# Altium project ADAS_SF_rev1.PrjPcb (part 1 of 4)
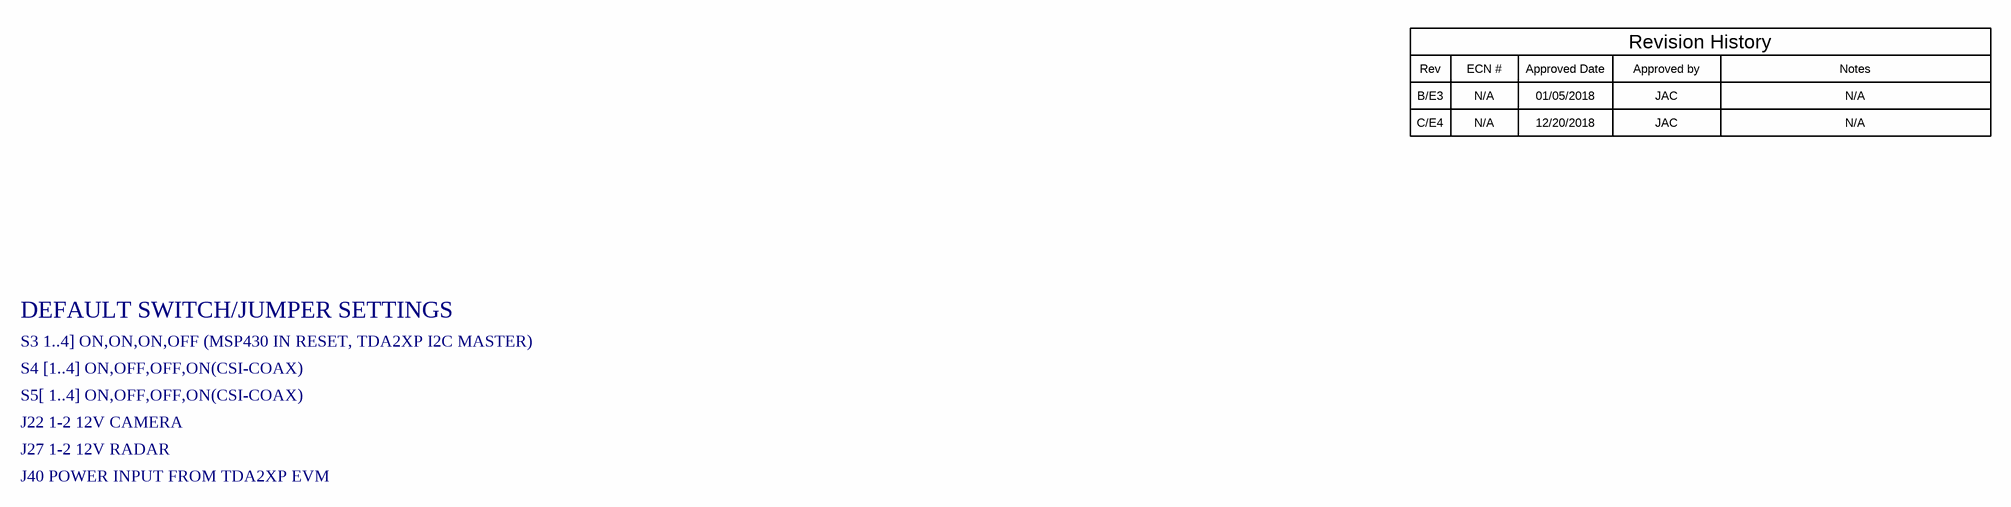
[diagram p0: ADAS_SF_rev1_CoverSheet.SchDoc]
CopyrightYear: 2018; PCB_Layout: Spectrum Digital; PCB_Rev: C; PRJ_Customer: Public Release; PRJ_Engineer: Spectrum Digital; PRJ_Number: 518520C; PRJ_Title: ADAS Sensor Fusion Board; SCH_Rev: E4; TechSupport: http://www.ti.com/support; TID: N/A
15 sheets, 822 parts. Net scope: global (net labels, ports and power ports of the same name join across sheets).
Board file: PCB1_test.PcbDoc
Sheets:
  ADAS_SF_rev1_CoverSheet.SchDoc
  ADAS_SF_Power_Battery_Input.SchDoc
  ADAS_SF_Power_Buck_5V.SchDoc
  ADAS_SF_Power_Boost_12V.SchDoc
  ADAS_SF_Power_Buck_3V3_1V8_1V1.SchDoc
  ADAS_SF_Data_MSP430.SchDoc
  ADAS_SF_Data_Deserializer_Camera.SchDoc
  ADAS_SF_Data_Deserializer_Radar.SchDoc
  ADAS_SF_Data_Radar_Mux.SchDoc
  ADAS_SF_Data_Connection_Radar_01.SchDoc
  ADAS_SF_Data_Connection_Radar_02.SchDoc
  ADAS_SF_Data_Connection_Cam_01.SchDoc
  ADAS_SF_Data_Connection_Cam_02.SchDoc
  ADAS_SF_Data_CSI2_Connector.SchDoc
  ADAS_SF_rev1_Hardware.SchDoc

## Sheet ADAS_SF_rev1_CoverSheet.SchDoc
size 431 x 279 mm; Date: Not shown in title block; ApprovedBy: Not shown in title block; CheckedBy: Not shown in title block; Author: Not shown in title block; CompanyName: Not shown in title block; Engineer: Not shown in title block; Organization: Not shown in title block; Address1: Not shown in title block; Address2: Not shown in title block; Address3: Not shown in title block; Address4: Not shown in title block; DocumentNumber: 1; Revision: Use project parameter SCH_Rev; SheetNumber: 1; SheetTotal: 15; PageSetup: Record=PageOptions¦CenterHorizontal=True¦CenterVertical=True¦PrintScale=1.00¦XCorrection=1.00¦YCorrection=1.00¦PrintKind=0¦BorderSize=5000000¦LeftOffset=0¦BottomOffset=0¦Orientation=2¦PaperLength=1000¦PaperWidth=1000¦Scale=100¦PaperSource=15¦PrintQuality=600¦MediaType=1¦DitherType=10¦PaperKind=Letter¦PrintScaleMode=1

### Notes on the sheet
- Rev
- B/E3
- ECN #
- N/A
- Approved Date
- 01/05/2018
- Approved by
- JAC
- Revision History
- Notes
- C/E4
- 12/20/2018
- S3 1..4] ON,ON,ON,OFF (MSP430 IN RESET, TDA2XP I2C MASTER)
- DEFAULT SWITCH/JUMPER SETTINGS
- S4 [1..4] ON,OFF,OFF,ON(CSI-COAX)
- S5[ 1..4] ON,OFF,OFF,ON(CSI-COAX)
- J22 1-2 12V CAMERA
- J27 1-2 12V RADAR
- J40 POWER INPUT FROM TDA2XP EVM

## Sheet ADAS_SF_Power_Battery_Input.SchDoc
size 431 x 279 mm; Date: Not shown in title block; ApprovedBy: Not shown in title block; CheckedBy: Not shown in title block; Author: Not shown in title block; CompanyName: Not shown in title block; Engineer: Not shown in title block; Organization: Not shown in title block; Address1: Not shown in title block; Address2: Not shown in title block; Address3: Not shown in title block; Address4: Not shown in title block; DocumentNumber: 1; Revision: Use project parameter SCH_Rev; SheetNumber: 2; SheetTotal: 15; PageSetup: Record=PageOptions¦CenterHorizontal=True¦CenterVertical=True¦PrintScale=1.00¦XCorrection=1.00¦YCorrection=1.00¦PrintKind=0¦BorderSize=5000000¦LeftOffset=0¦BottomOffset=0¦Orientation=2¦PaperLength=1000¦PaperWidth=1000¦Scale=100¦PaperSource=15¦PrintQuality=600¦MediaType=1¦DitherType=10¦PaperKind=Letter¦PrintScaleMode=1
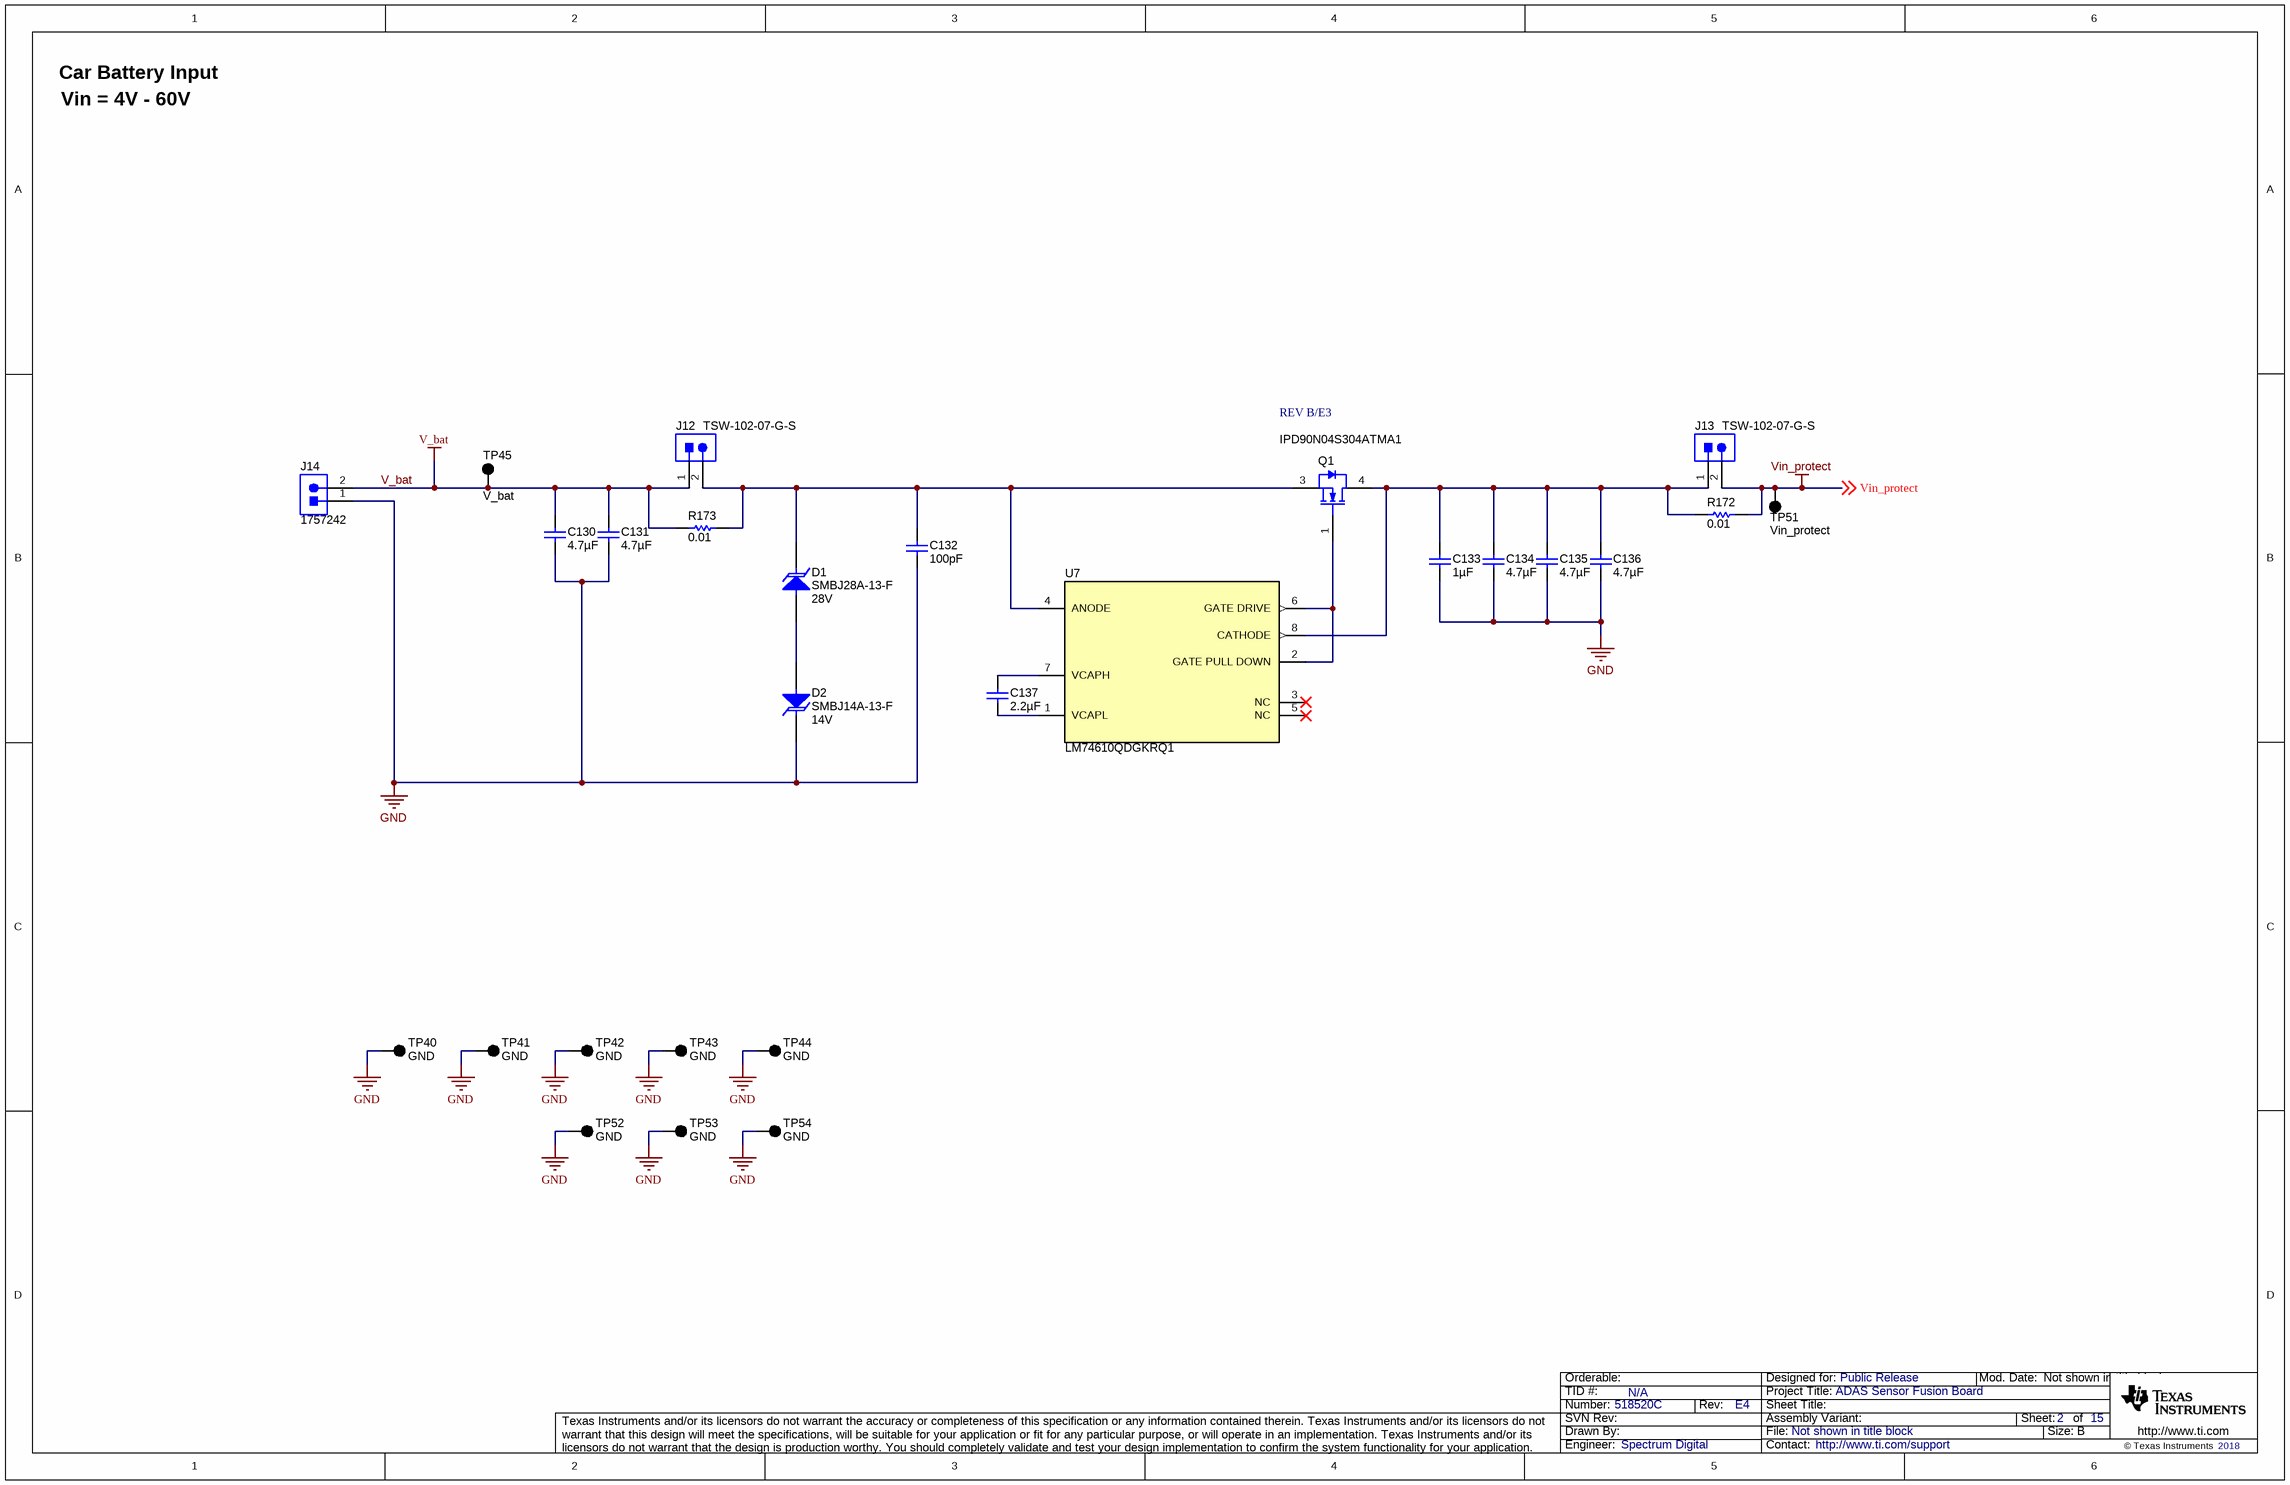
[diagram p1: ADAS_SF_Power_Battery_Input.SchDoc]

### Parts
C130  ValueDisplayed: 4.7µF  [1210_220]  (hidden comment: C3225X7S2A475K200AB)
C131  ValueDisplayed: 4.7µF  [1210_220]  (hidden comment: C3225X7S2A475K200AB)
C132  ValueDisplayed: 100pF  [0805_HV]  (hidden comment: 08055A101JAT2A)
C133  ValueDisplayed: 1µF  [0805_HV]  (hidden comment: GRM21BR71H105KA12L)
C134  ValueDisplayed: 4.7µF  [0805_HV]  (hidden comment: GRM21BC71H475KE11K)
C135  ValueDisplayed: 4.7µF  [0805_HV]  (hidden comment: GRM21BC71H475KE11K)
C136  ValueDisplayed: 4.7µF  [0805_HV]  (hidden comment: GRM21BC71H475KE11K)
C137  ValueDisplayed: 2.2µF  [0805_HV]  (hidden comment: C2012X5R1H225K125AB)
D1  SMBJ28A-13-F  value 28V  [SMB]
D2  SMBJ14A-13-F  value 14V  [SMB]
J12  TSW-102-07-G-S  [TSW-102-07-G-S]
J13  TSW-102-07-G-S  [TSW-102-07-G-S]
J14  1757242  [PHOENIX_1757242]
Q1  IPD90N04S304ATMA1  [DPAK]
R172  ValueDisplayed: 0.01  [KRL2012]  (hidden comment: KRL2012E-M-R010-F-T5)
R173  ValueDisplayed: 0.01  [KRL2012]  (hidden comment: KRL2012E-M-R010-F-T5)
TP40  GND  [Keystone5011]
TP41  GND  [Keystone5011]
TP42  GND  [Keystone5011]
TP43  GND  [Keystone5011]
TP44  GND  [Keystone5011]
TP45  V_bat  [Keystone5011]
TP51  Vin_protect  [Keystone5011]
TP52  GND  [Keystone5011]
TP53  GND  [Keystone5011]
TP54  GND  [Keystone5011]
U7  LM74610QDGKRQ1  [DGK0008A_N]

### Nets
GND: C130.2 C131.2 C132.2 C133.2 C134.2 C135.2 C136.2 D2.1(K) J14.1 TP40.1 TP41.1 TP42.1 TP43.1 TP44.1 TP52.1 TP53.1 TP54.1
V_bat: C130.1 C131.1 J12.1 J14.2 R173.1 TP45.1
Vin_protect: J13.2 R172.2 TP51.1 ; off-sheet Vin_protect
NetC132_1: C132.1 D1.1(K) J12.2 Q1.3(S) R173.2 U7.4(ANODE)
NetC133_1: C133.1 C134.1 C135.1 C136.1 J13.1 Q1.4(D) R172.1 U7.8(CATHODE)
NetC137_1: C137.1 U7.7(VCAPH)
NetC137_2: C137.2 U7.1(VCAPL)
NetD1_2: D1.2(A) D2.2(A)
NetQ1_1: Q1.1(G) U7.2(GATE_PULL_DOWN) U7.6(GATE_DRIVE)

Not connected (* = marked no-connect by the designer): U7 3(NC)* 5(NC)*

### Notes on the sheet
- Vin = 4V - 60V
- Car Battery Input
- REV B/E3

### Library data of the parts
C130 C131 = C3225X7S2A475K200AB: CAP, CERM, 4.7 µF, 100 V, +/- 10%, X7S, 1210; Manufacturer: TDK; Polarized: N; CompType: Capacitor; Value: 4.7uF; U/M: EA; Cap_F: 0.0000047; Tolerance_%: 10; ESR_ohm: 0.004236; Value1: 0.004236 ohm; VDC_V: 100; Value2: 100V; IRMS_A: 3.57337; TaMin_C: -55; TaMax_C: 125; SizeArea_mm2: 8; SizeAreaWB_mm2: 14.7; SizeX_mm: 3.2; SizeY_mm: 2.5; SizeZ_mm: 2.2; AEC Category: Q200
C132 = 08055A101JAT2A: CAP, CERM, 100 pF, 50 V, +/- 5%, C0G/NP0, 0805; Manufacturer: AVX; Polarized: N; CompType: Capacitor; Value: 100pF; U/M: EA; Cap_F: 0.0000000001; Tolerance_%: 5; ESR_ohm: 0.356; Value1: 0.356 ohm; VDC_V: 50; Value2: 50V; TaMin_C: -55; TaMax_C: 125; Cap_Case: 0805; AEC Category: Q200
C133 = GRM21BR71H105KA12L: CAP, CERM, 1 µF, 50 V, +/- 10%, X7R, 0805; Manufacturer: MuRata; Polarized: N; CompType: Capacitor; Value: 1uF; U/M: EA; Cap_F: 0.000001; Tolerance_%: 10; Value1: Unknown; VDC_V: 50; Value2: 50V; TaMin_C: -55; TaMax_C: 125; Cap_Case: 0805; SizeArea_mm2: 2.5; SizeAreaWB_mm2: 6.75; SizeX_mm: 2; SizeY_mm: 1.25; SizeZ_mm: 1.45; AEC Category: Q200
C134-C136 = GRM21BC71H475KE11K: CAP, CERM, 4.7 µF, 50 V, +/- 10%, X7S, 0805; Manufacturer: MuRata; Polarized: N; CompType: Capacitor; Value: 4.7uF; U/M: EA; Cap_F: 0.0000047; Tolerance_%: 10; Value1: Unknown; VDC_V: 50; Value2: 50V; TaMin_C: -55; TaMax_C: 125; Cap_Case: 0805; SizeArea_mm2: 2.5; SizeAreaWB_mm2: 6.75; SizeX_mm: 2; SizeY_mm: 1.25; SizeZ_mm: 1.45; AEC Category: Q200
C137 = C2012X5R1H225K125AB: CAP, CERM, 2.2 µF, 50 V, +/- 10%, X5R, 0805; Manufacturer: TDK; Polarized: N; CompType: Capacitor; Value: 2.2uF; U/M: EA; Cap_F: 0.0000022; Tolerance_%: 10; Value1: Unknown; VDC_V: 50; Value2: 50V; TaMin_C: -55; TaMax_C: 85; Cap_Case: 0805; AEC Category: Q200
D1 = SMBJ28A-13-F: Diode, TVS, Uni, 28 V, 600 W, SMB; Manufacturer: Diodes Inc.; U/M: EA; Power_W: 5; Vr_V: 28; Value1: 5W; AEC Category: Q101
D2 = SMBJ14A-13-F: Diode, TVS, Uni, 14 V, 600 W, SMB; Manufacturer: Diodes Inc.; U/M: EA; Power_W: 5; Vr_V: 14; Value1: 5W; AEC Category: Q101
J12 J13 = TSW-102-07-G-S: Header, 100mil, 2x1, Gold, TH; Manufacturer: Samtec; SymbolCreator: a0412235; Pitch_mm: 2.54; Gender: Male; Shrouded: N; Row_Count: 1; Current_A: 6.3; Voltage_V: 550; Cert_CSA: Y
J14 = 1757242: Header (Shrouded), 5.08 mm, 2x1, Tin, R/A, TH; Manufacturer: Phoenix Contact; SymbolCreator: a0412235
Q1 = IPD90N04S304ATMA1: MOSFET, N-CH, 40 V, 90 A, AEC-Q101, DPAK; Manufacturer: Infineon Technologies; Alternate Manufacturer: None; U/M: EA; ChType: N; Value: 40V; VdsMax_V: 40; Value1: ? ohm; Value2: 60 nC; QgTyp_nC: 60; Vgs_V: 20; IdsMax_A: 90; AEC Category: Q101; AEC Qualified: Y
R172 R173 = KRL2012E-M-R010-F-T5: RES, 0.01, 1%, 1 W, AEC-Q200 Grade 0, 0508; Manufacturer: Susumu Co Ltd; CompType: Resistor; Value: 0.01; Value_Code: R010; Tolerance_%: 1; Value2: 1W; TempCo: 25 ppm/C; EIA_Code: E96; U/M: EA; AEC Category: Q200; AEC Qualified: Y; AEC Grade: 0
TP40-TP45 TP51-TP54 = 5011: Test Point, Multipurpose, Black, TH; Manufacturer: Keystone; CompType: Test Point Loop; U/M: EA
U7 = LM74610QDGKRQ1: Smart Diode Controller, DGK0008A; Manufacturer: Texas Instruments; SymbolCreator: Altium; CompType: IC; U/M: EA

## Sheet ADAS_SF_Power_Buck_5V.SchDoc
size 431 x 279 mm; Date: Not shown in title block; ApprovedBy: Not shown in title block; CheckedBy: Not shown in title block; Author: Not shown in title block; CompanyName: Not shown in title block; Engineer: Not shown in title block; Organization: Not shown in title block; Address1: Not shown in title block; Address2: Not shown in title block; Address3: Not shown in title block; Address4: Not shown in title block; DocumentNumber: 1; Revision: Use project parameter SCH_Rev; SheetNumber: 3; SheetTotal: 15; PageSetup: Record=PageOptions¦CenterHorizontal=True¦CenterVertical=True¦PrintScale=0.66¦XCorrection=1.00¦YCorrection=1.00¦PrintKind=0¦BorderSize=5000000¦LeftOffset=0¦BottomOffset=0¦Orientation=2¦PaperLength=1000¦PaperWidth=1000¦Scale=100¦PaperSource=15¦PrintQuality=600¦MediaType=1¦DitherType=10¦PrintScaleMode=1¦PaperKind=Letter
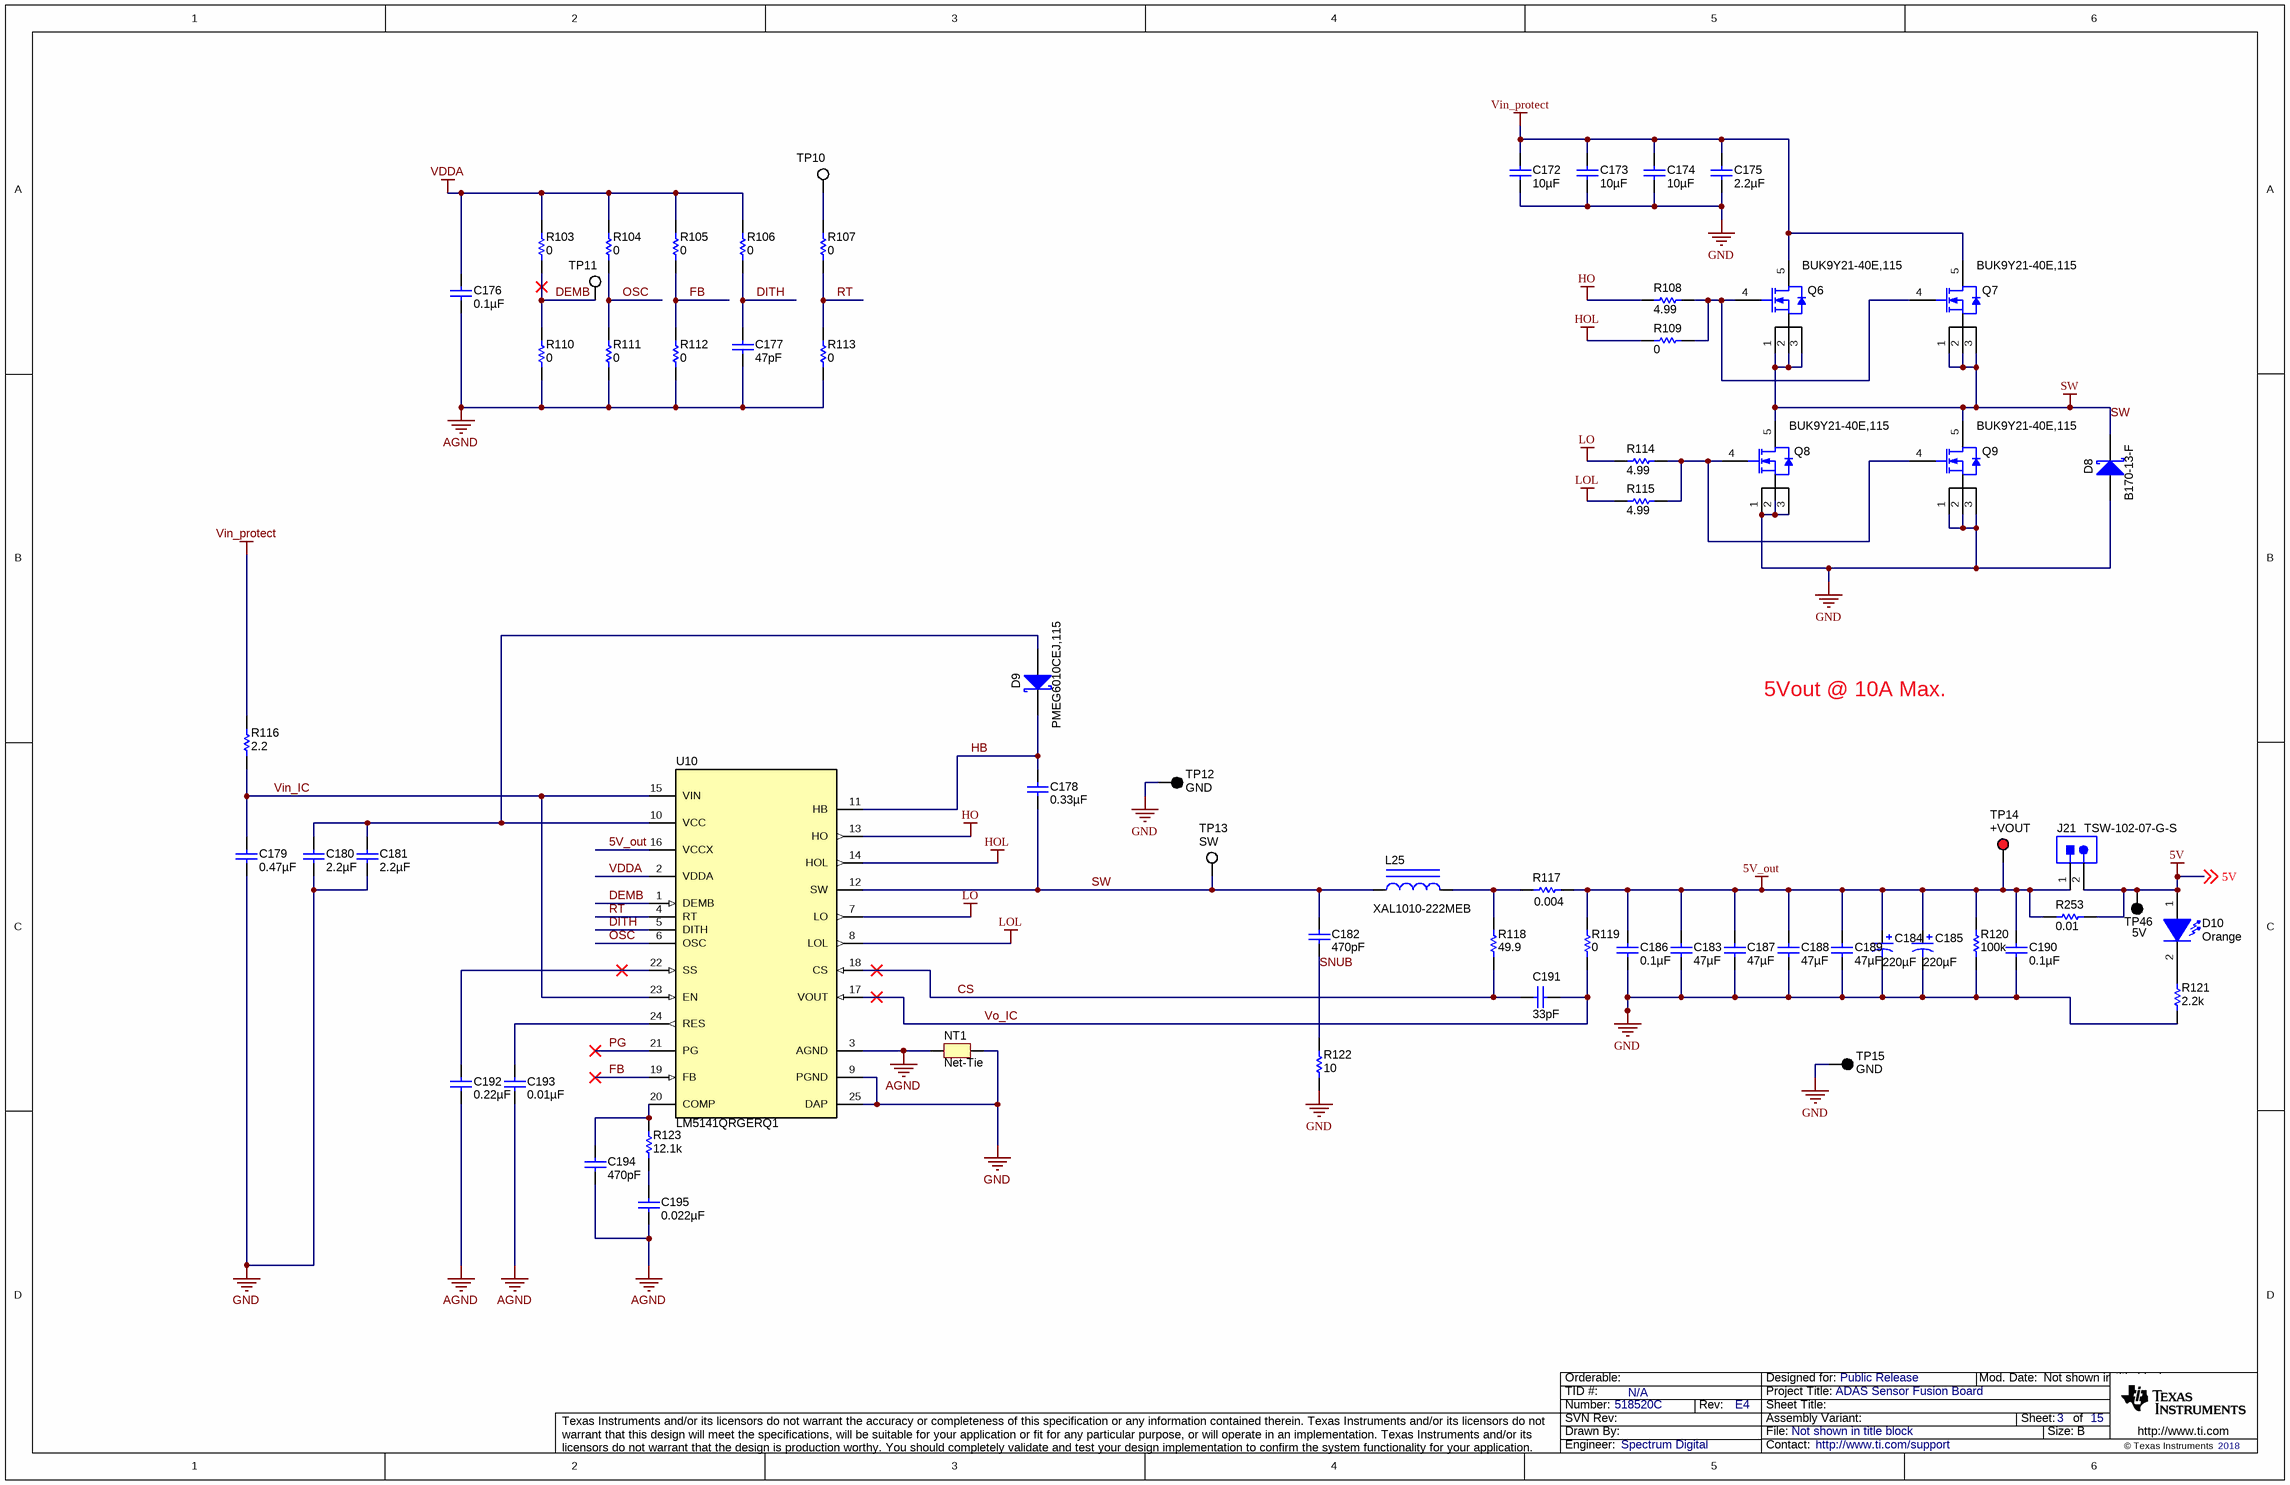
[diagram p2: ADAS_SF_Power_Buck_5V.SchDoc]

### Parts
C172  ValueDisplayed: 10µF  [1206_190]  (hidden comment: CGA5L3X5R1H106K160AB)
C173  ValueDisplayed: 10µF  [1206_190]  (hidden comment: CGA5L3X5R1H106K160AB)
C174  ValueDisplayed: 10µF  [1206_190]  (hidden comment: CGA5L3X5R1H106K160AB)
C175  2.2µF  [1206]
C176  ValueDisplayed: 0.1µF  [0402]  (hidden comment: GCM155R71H104KE02D)
C177  ValueDisplayed: 47pF  [0402]  (hidden comment: GRM1555C1E470JA01D)
C178  ValueDisplayed: 0.33µF  [0805_HV]  (hidden comment: GRM21AR72A334KAC5L)
C179  ValueDisplayed: 0.47µF  [0805_HV]  (hidden comment: GRM21BR72A474KA73L)
C180  ValueDisplayed: 2.2µF  [0603_HV]  (hidden comment: C0603C225M8PACTU)
C181  ValueDisplayed: 2.2µF  [0603_HV]  (hidden comment: C0603C225M8PACTU)
C182  ValueDisplayed: 470pF  [0805_HV]  (hidden comment: 08051A471JAT2A)
C183  ValueDisplayed: 47µF  [1206_180]  (hidden comment: GRM31CR61A476KE15L)
C184  ValueDisplayed: 220µF  [CAPSMT_62_H70]  (hidden comment: APXA6R3ARA221MH70G)
C185  ValueDisplayed: 220µF  [CAPSMT_62_H70]  (hidden comment: APXA6R3ARA221MH70G)
C186  ValueDisplayed: 0.1µF  [0603L]  (hidden comment: GRM188R72A104KA35D)
C187  ValueDisplayed: 47µF  [1206_180]  (hidden comment: GRM31CR61A476KE15L)
C188  ValueDisplayed: 47µF  [1206_180]  (hidden comment: GRM31CR61A476KE15L)
C189  ValueDisplayed: 47µF  [1206_180]  (hidden comment: GRM31CR61A476KE15L)
C190  ValueDisplayed: 0.1µF  [0603L]  (hidden comment: GRM188R72A104KA35D)
C191  ValueDisplayed: 33pF  [0603L]  (hidden comment: 06031A330JAT2A)
C192  ValueDisplayed: 0.22µF  [0402]  (hidden comment: GRM155R61A224KE19D)
C193  ValueDisplayed: 0.01µF  [0402]  (hidden comment: GCM155R71H103KA55D)
C194  ValueDisplayed: 470pF  [0402]  (hidden comment: GRM1555C1E471JA01D)
C195  ValueDisplayed: 0.022µF  [0402]  (hidden comment: GRM155R71C223KA01D)
D8  B170-13-F  [SMA]
D9  PMEG6010CEJ,115  [SOD-323F]
D10  value Orange  [LED_SMLP12_ORANGE]  (hidden comment: SML-P12DTT86)
J21  TSW-102-07-G-S  [TSW-102-07-G-S]
L25  XAL1010-222MEB  [XAL1010]
NT1  Net-Tie  [Net-Tie_10mil]  (net tie, no BOM)
Q6  BUK9Y21-40E,115  [LFPAK56]
Q7  BUK9Y21-40E,115  [LFPAK56]
Q8  BUK9Y21-40E,115  [LFPAK56]
Q9  BUK9Y21-40E,115  [LFPAK56]
R103  ValueDisplayed: 0  [0402]  (hidden comment: CRCW04020000Z0ED)
R104  ValueDisplayed: 0  [0402]  (hidden comment: CRCW04020000Z0ED)
R105  ValueDisplayed: 0  [0402]  (hidden comment: CRCW04020000Z0ED)
R106  ValueDisplayed: 0  [0402]  (hidden comment: CRCW04020000Z0ED)
R107  ValueDisplayed: 0  [0402]  (hidden comment: CRCW04020000Z0ED)
R108  ValueDisplayed: 4.99  [0603L]  (hidden comment: CRCW06034R99FKEA)
R109  ValueDisplayed: 0  [0603L]  (hidden comment: CRCW06030000Z0EA)
R110  ValueDisplayed: 0  [0402]  (hidden comment: CRCW04020000Z0ED)
R111  ValueDisplayed: 0  [0402]  (hidden comment: CRCW04020000Z0ED)
R112  ValueDisplayed: 0  [0402]  (hidden comment: CRCW04020000Z0ED)
R113  ValueDisplayed: 0  [0402]  (hidden comment: CRCW04020000Z0ED)
R114  ValueDisplayed: 4.99  [0603L]  (hidden comment: CRCW06034R99FKEA)
R115  ValueDisplayed: 4.99  [0603L]  (hidden comment: CRCW06034R99FKEA)
R116  ValueDisplayed: 2.2  [0603L]  (hidden comment: CRCW06032R20JNEA)
R117  value 0.004  [2010]  (hidden comment: PMR50HZPFV4L00)
R118  ValueDisplayed: 49.9  [0603L]  (hidden comment: CRCW060349R9FKEA)
R119  ValueDisplayed: 0  [0603L]  (hidden comment: CRCW06030000Z0EA)
R120  ValueDisplayed: 100k  [0805_HV]  (hidden comment: CRCW0805100KFKEA)
R121  ValueDisplayed: 2.2k  [0402]  (hidden comment: CRCW04022K20JNED)
R122  ValueDisplayed: 10  [2010]  (hidden comment: CRCW201010R0JNEF)
R123  ValueDisplayed: 12.1k  [0402]  (hidden comment: CRCW040212K1FKED)
R253  ValueDisplayed: 0.01  [KRL2012]  (hidden comment: KRL2012E-M-R010-F-T5)
TP10  5012  [Keystone5012]  (value not drawn)
TP11  5012  [Keystone5012]  (value not drawn)
TP12  GND  [Keystone5011]
TP13  SW  [Keystone5012]
TP14  +VOUT  [Keystone5010]
TP15  GND  [Keystone5011]
TP46  5V  [Keystone5011]
U10  LM5141QRGERQ1  [RGE0024H]

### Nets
5V: D10.1(A) J21.2 R253.2 TP46.1 ; off-sheet 5V
5V_out: C183.1 C184.1(+) C185.1(+) C186.2 C187.1 C188.1 C189.1 C190.2 J21.1 R117.2 R119.2 R120.2 R253.1 TP14.1 U10.16(VCCX)
AGND: C176.2 C177.1 C192.2 C193.2 C194.1 C195.2 NT1.2 R110.1 R111.1 R112.1 R113.1 U10.3(AGND)
GND: C172.2 C173.2 C174.2 C175.2 C179.1 C180.2 C181.1 C183.2 C184.2(-) C185.2(-) C186.1 C187.2 C188.2 C189.2 C190.1 D8.2(A) NT1.1 Q8.1(S) Q8.2(S) Q8.3(S) Q9.1(S) Q9.2(S) Q9.3(S) R120.1 R121.2 R122.1 TP12.1 TP15.1 U10.9(PGND) U10.25(DAP)
HO: R108.1 U10.13(HO)
HOL: R109.1 U10.14(HOL)
LO: R114.1 U10.7(LO)
LOL: R115.1 U10.8(LOL)
SW: C178.1 C182.2 D8.1(K) L25.1 Q6.1(S) Q6.2(S) Q6.3(S) Q7.1(S) Q7.2(S) Q7.3(S) Q8.5(D) Q9.5(D) TP13.1 U10.12(SW)
VDDA: C176.1 R103.2 R104.2 R105.2 R106.2 U10.2(VDDA)
Vin_protect: C172.1 C173.1 C174.1 C175.1 Q6.5(D) Q7.5(D) R116.2
CS: C191.2 R118.1 U10.18(CS)
DEMB: R103.1 R110.2 TP11.1 U10.1(DEMB)
DITH: C177.2 R106.1 U10.5(DITH)
FB: R105.1 R112.2 U10.19(FB)
HB: C178.2 D9.1(K) U10.11(HB)
OSC: R104.1 R111.2 U10.6(OSC)
PG: U10.21(PG)
RT: R107.1 R113.2 U10.4(RT)
SNUB: C182.1 R122.2
Vin_IC: C179.2 R116.1 U10.15(VIN) U10.23(EN)
Vo_IC: C191.1 R119.1 U10.17(VOUT)
NetC180_1: C180.1 C181.2 D9.2(A) U10.10(VCC)
NetC192_1: C192.1 U10.22(SS)
NetC193_1: C193.1 U10.24(RES)
NetC194_2: C194.2 R123.2 U10.20(COMP)
NetC195_1: C195.1 R123.1
NetD10_2: D10.2(K) R121.1
NetL25_2: L25.2 R117.1 R118.2
NetQ6_4: Q6.4(G) Q7.4(G) R108.2 R109.2
NetQ8_4: Q8.4(G) Q9.4(G) R114.2 R115.2
NetR107_2: R107.2 TP10.1

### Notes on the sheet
- 5Vout @ 10A Max.

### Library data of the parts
C172-C174 = CGA5L3X5R1H106K160AB: CAP, CERM, 10 µF, 50 V, +/- 10%, X5R, 1206_190; Manufacturer: TDK; Polarized: N; CompType: Capacitor; Value: 10uF; U/M: EA; Cap_F: 0.00001; Tolerance_%: 10; Value1: Unknown; VDC_V: 50; Value2: 50V; TaMin_C: -55; TaMax_C: 85; Cap_Case: 1206
C175 = CL31B225KCHSNNE: CAP CER 2.2UF 100V 10% X7R 1206; Manufacturer: Samsung Electro-Mechanics America, Inc; SymbolVersion: use current date i.e. 2008-05-20; SymbolCreator: Use a-id; CompType: Used in some BOM reports.  Useful for finding later.; U/M: EA, IN, or GM
C176 = GCM155R71H104KE02D: CAP, CERM, 0.1 µF, 50 V, +/- 10%, X7R, AEC-Q200 Grade 1, 0402; Manufacturer: MuRata; Polarized: N; CompType: Capacitor; Value: 0.1uF; U/M: EA; Cap_F: 0.0000001; Tolerance_%: 10; Value1: Unknown; VDC_V: 50; Value2: 50V; TaMin_C: -55; TaMax_C: 125; AEC Category: Q200; AEC Qualified: Y; AEC Grade: 1; SizeArea_mm2: 0.5; SizeAreaWB_mm2: 3; SizeZ_mm: 0.6
C177 = GRM1555C1E470JA01D: CAP, CERM, 47 pF, 25 V, +/- 5%, C0G/NP0, 0402; Manufacturer: MuRata; Polarized: N; CompType: Capacitor; Value: 47pF; U/M: EA; Cap_F: 0.000000000047; Tolerance_%: 5; Value1: Unknown; VDC_V: 25; Value2: 25V; TaMin_C: -55; TaMax_C: 125; AEC Category: Q200
C178 = GRM21AR72A334KAC5L: CAP, CERM, 0.33 µF, 100 V, +/- 10%, X7R, 0805; Manufacturer: MuRata; Polarized: N; CompType: Capacitor; Value: 0.33uF; U/M: EA; Cap_F: 0.00000033; Tolerance_%: 10; Value1: Unknown; VDC_V: 100; Value2: 100V; TaMin_C: -55; TaMax_C: 125; Cap_Case: 0805
C179 = GRM21BR72A474KA73L: CAP, CERM, 0.47uF, 100V, +/-10%, X7R, 0805; Manufacturer: MuRata; Polarized: N; CompType: Capacitor; U/M: EA; Cap_F: 0.00000047; Tolerance_%: 10; Value1: Unknown; VDC_V: 100; TaMin_C: -55; TaMax_C: 125; Cap_Case: 0805
C180 C181 = C0603C225M8PACTU: CAP, CERM, 2.2 µF, 10 V, +/- 20%, X5R, 0603; Manufacturer: Kemet; Polarized: N; CompType: Capacitor; Value: 2.2uF; U/M: EA; Cap_F: 0.0000022; Tolerance_%: 20; Value1: Unknown; VDC_V: 10; Value2: 10V; TaMin_C: -55; TaMax_C: 85; Cap_Case: 0603
C182 = 08051A471JAT2A: CAP, CERM, 470 pF, 100 V, +/- 5%, C0G/NP0, 0805; Manufacturer: AVX; Polarized: N; CompType: Capacitor; Value: 470pF; U/M: EA; Cap_F: 0.00000000047; Tolerance_%: 5; ESR_ohm: 0.159; Value1: 0.159 ohm; VDC_V: 100; Value2: 100V; TaMin_C: -55; TaMax_C: 125; Cap_Case: 0805; SizeArea_mm2: 2.5; SizeAreaWB_mm2: 6.75; SizeX_mm: 2; SizeY_mm: 1.25; SizeZ_mm: 1.45; AEC Category: Q200
C183 C187-C189 = GRM31CR61A476KE15L: CAP, CERM, 47 µF, 10 V, +/- 10%, X5R, 1206; Manufacturer: MuRata; Polarized: N; CompType: Capacitor; Value: 47uF; U/M: EA; Cap_F: 0.000047; Tolerance_%: 10; Value1: Unknown; Value2: 10V; TaMin_C: -55; TaMax_C: 85; Cap_Case: 1206; SizeArea_mm2: 5.12; SizeAreaWB_mm2: 10.92; SizeX_mm: 3.2; SizeY_mm: 1.6; SizeZ_mm: 1.8; AEC Category: Q200
C184 C185 = APXA6R3ARA221MH70G: CAP, AL, 220 µF, 6.3 V, +/- 20%, 0.025 ohm, SMD; Manufacturer: Chemi-Con; Polarized: Y; CompType: Capacitor; Value: 220uF; U/M: EA; Cap_F: 0.00022; Tolerance_%: 20; VDC_V: 6.3; Value2: 6.3V; ESR_ohm: 0.025; IRMS_A: 3.02; TaMin_C: -55; TaMax_C: 105; Cap_Case: H70
C186 C190 = GRM188R72A104KA35D: CAP, CERM, 0.1uF, 100V, +/-10%, X7R, 0603; Manufacturer: MuRata; Polarized: N; CompType: Capacitor; U/M: EA; Cap_F: 0.0000001; Tolerance_%: 10; Value1: Unknown; VDC_V: 100; TaMin_C: -55; TaMax_C: 125; Cap_Case: 0603
C191 = 06031A330JAT2A: CAP, CERM, 33 pF, 100 V, +/- 5%, C0G/NP0, 0603; Manufacturer: AVX; Polarized: N; CompType: Capacitor; Value: 33pF; U/M: EA; Cap_F: 0.000000000033; Tolerance_%: 5; ESR_ohm: 0.209; Value1: 0.209 ohm; VDC_V: 100; Value2: 100V; TaMin_C: -55; TaMax_C: 125; Cap_Case: 0603
C192 = GRM155R61A224KE19D: CAP, CERM, 0.22 µF, 10 V, +/- 10%, X5R, 0402; Manufacturer: MuRata; Polarized: N; CompType: Capacitor; Value: 0.22uF; U/M: EA; Cap_F: 0.00000022; Tolerance_%: 10; Value1: Unknown; Value2: 10V; TaMin_C: -55; TaMax_C: 85; SizeArea_mm2: 0.5; SizeAreaWB_mm2: 3; SizeX_mm: 1; SizeZ_mm: 0.6; AEC Category: Q200
C193 = GCM155R71H103KA55D: CAP, CERM, 0.01uF, 50V, +/-10%, C0G/NP0, 0402; Manufacturer: MuRata; Polarized: N; CompType: Capacitor; U/M: EA; Cap_F: 0.00000001; Tolerance_%: 10; Value1: Unknown; VDC_V: 50; TaMin_C: -55; TaMax_C: 125
C194 = GRM1555C1E471JA01D: CAP, CERM, 470 pF, 25 V, +/- 5%, C0G/NP0, 0402; Manufacturer: MuRata; Polarized: N; CompType: Capacitor; Value: 470pF; U/M: EA; Cap_F: 0.00000000047; Tolerance_%: 5; Value1: Unknown; VDC_V: 25; Value2: 25V; TaMin_C: -55; TaMax_C: 125; SizeArea_mm2: 0.5; SizeAreaWB_mm2: 3; SizeX_mm: 1; SizeZ_mm: 0.6; AEC Category: Q200
C195 = GRM155R71C223KA01D: CAP, CERM, 0.022 µF, 16 V, +/- 10%, X7R, 0402; Manufacturer: MuRata; Polarized: N; CompType: Capacitor; Value: 0.022uF; U/M: EA; Cap_F: 0.000000022; Tolerance_%: 10; Value1: Unknown; VDC_V: 16; Value2: 16V; TaMin_C: -55; TaMax_C: 125; SizeArea_mm2: 0.5; SizeAreaWB_mm2: 3; SizeX_mm: 1; SizeZ_mm: 0.6; AEC Category: Q200
D8 = B170-13-F: Diode, Schottky, 70V, 1A, SMA; Manufacturer: Diodes Inc.; U/M: EA; Vr_V: 70; Io_A: 1; Vf_V: 0.79; Value2: 0.79V; TJmax_C: 150; RJC_CperW: 25
D9 = PMEG6010CEJ,115: Diode, Schottky, 60 V, 1 A, SOD-323F; Manufacturer: NXP Semiconductor; U/M: EA; Vf_V: 0.66; Value: 60V; Value1: 1A; Value2: 0.66V; Io_A: 1; Vr_V: 60; TJmax_C: 150
D10 = SML-P12DTT86: LED, Orange, SMD; Manufacturer: Rohm; Type: InGaN; Vf_V: 2.1; Value2: 2.1V; Io_A: 0.02; Tjmax_C: 85; Value1: W; U/M: EA
J21 = TSW-102-07-G-S: as J12 on sheet ADAS_SF_Power_Battery_Input
L25 = XAL1010-222MEB: Inductor, Shielded, Composite, 2.2 µH, 32 A, 0.00255 ohm, SMD; Manufacturer: Coilcraft; Value: 2.2uH; Ind_H: 2.2E-6; ValueDisplayed: 2.2µH; Imax_A: 32; Irms: 32A @ 40C rise; Isat: 34A @ 30% inductance drop; Value2: 32A
NT1 = Net-Tie: Single point connection between nets.; SymbolCreator: codlsc
Q6-Q9 = BUK9Y21-40E,115: MOSFET, N-CH, 40 V, 33 A, AEC-Q101, SOT669; Manufacturer: NXP Semiconductor; Alternate Manufacturer: None; SymbolCreator: a0412235; U/M: EA; ChType: N; Value: 40V; VdsMax_V: 40; Value1: ? ohm; Value2: 7 nC; QgTyp_nC: 7; Vgs_V: 10; IdsMax_A: 33; AEC Category: Q101; AEC Qualified: Y
R103-R107 R110-R113 = CRCW04020000Z0ED: RES, 0, 5%, 0.063 W, 0402; Manufacturer: Vishay-Dale; CompType: Resistor; Value: 0; Value_Code: 0000; Tolerance_%: 5; Power_W: 0.063; Value2: 0.063W; VDC_V: 50; TempCo: 200 ppm/C; EIA_Code: E24; U/M: EA; AEC Category: Q200
R108 R114 R115 = CRCW06034R99FKEA: RES, 4.99, 1%, 0.1 W, 0603; Manufacturer: Vishay-Dale; CompType: Resistor; Value: 4.99; Value_Code: 4R99; Tolerance_%: 1; Power_W: 0.1; Value2: 0.1W; VDC_V: 75; TempCo: 100 ppm/C; EIA_Code: E96; U/M: EA
R109 R119 = CRCW06030000Z0EA: RES, 0, 5%, 0.1 W, 0603; Manufacturer: Vishay-Dale; CompType: Resistor; Value: 0; Value_Code: 0000; Tolerance_%: 5; Power_W: 0.1; Value2: 0.1W; VDC_V: 75; TempCo: 200 ppm/C; EIA_Code: E24; U/M: EA
R116 = CRCW06032R20JNEA: RES, 2.2, 5%, 0.1 W, 0603; Manufacturer: Vishay-Dale; CompType: Resistor; Value: 2.2; Value_Code: 2R20; Tolerance_%: 5; Power_W: 0.1; Value2: 0.1W; VDC_V: 75; TempCo: 200 ppm/C; EIA_Code: E24; U/M: EA
R117 = Resistor: RES, 0.004 ohm, 1%, 1W, 2010, AEC-Q200 Qualified; Manufacturer: Rohm Semiconductor; U/M: EA
R118 = CRCW060349R9FKEA: RES, 49.9, 1%, 0.1 W, 0603; Manufacturer: Vishay-Dale; CompType: Resistor; Value: 49.9; Value_Code: 49R9; Tolerance_%: 1; Power_W: 0.1; Value2: 0.1W; VDC_V: 75; TempCo: 100 ppm/C; EIA_Code: E96; U/M: EA
R120 = CRCW0805100KFKEA: RES, 100 k, 1%, 0.125 W, 0805; Manufacturer: Vishay-Dale; CompType: Resistor; Value: 100k; Res_ohm: 100000; Tolerance_%: 1; Power_W: 0.125; Value2: 0.125W; VDC_V: 150; TempCo: 100 ppm/C; EIA_Code: E96; U/M: EA
R121 = CRCW04022K20JNED: RES, 2.2 k, 5%, 0.063 W, 0402; Manufacturer: Vishay-Dale; CompType: Resistor; Value: 2.2k; Res_ohm: 2200; Value_Code: 2k20; Tolerance_%: 5; Power_W: 0.063; Value2: 0.063W; VDC_V: 50; TempCo: 200 ppm/C; EIA_Code: E24; U/M: EA
R122 = CRCW201010R0JNEF: RES, 10, 5%, 0.75 W, 2010; Manufacturer: Vishay-Dale; CompType: Resistor; Value: 10; Value_Code: 10R0; Tolerance_%: 5; Power_W: 0.75; Value2: 0.75W; VDC_V: 400; TempCo: 200 ppm/C; EIA_Code: E24; U/M: EA
R123 = CRCW040212K1FKED: RES, 12.1 k, 1%, 0.063 W, 0402; Manufacturer: Vishay-Dale; CompType: Resistor; Value: 12.1k; Res_ohm: 12100; Value_Code: 12k1; Tolerance_%: 1; Power_W: 0.063; Value2: 0.063W; VDC_V: 50; TempCo: 100 ppm/C; SizeArea_mm2: 0.5; SizeZ_mm: 0.6; EIA_Code: E96; U/M: EA; AEC Category: Q200
R253 = KRL2012E-M-R010-F-T5: as R172 on sheet ADAS_SF_Power_Battery_Input
TP10 TP11 = 5012: Test Point, Multipurpose, White, TH; Manufacturer: Keystone; CompType: Test Point Loop; ContactFinish: Silver
TP12 TP15 TP46 = 5011: as TP40 on sheet ADAS_SF_Power_Battery_Input
TP13 = 5012: Test Point, Multipurpose, White, TH; Manufacturer: Keystone; CompType: Test Point Loop; U/M: EA
TP14 = 5010: Test Point, Multipurpose, Red, TH; Manufacturer: Keystone; CompType: Test Point Loop; U/M: EA
U10 = LM5141QRGERQ1: Wide Input Range Buck Controller, RGE0024H; Manufacturer: Texas Instruments; SymbolCreator: Altium; CompType: IC; U/M: EA

## Sheet ADAS_SF_Power_Boost_12V.SchDoc
size 431 x 279 mm; Date: Not shown in title block; ApprovedBy: Not shown in title block; CheckedBy: Not shown in title block; Author: Not shown in title block; CompanyName: Not shown in title block; Engineer: Not shown in title block; Organization: Not shown in title block; Address1: Not shown in title block; Address2: Not shown in title block; Address3: Not shown in title block; Address4: Not shown in title block; DocumentNumber: 1; Revision: Use project parameter SCH_Rev; SheetNumber: 4; SheetTotal: 15; PageSetup: Record=PageOptions¦CenterHorizontal=True¦CenterVertical=True¦PrintScale=1.00¦XCorrection=1.00¦YCorrection=1.00¦PrintKind=0¦BorderSize=5000000¦LeftOffset=0¦BottomOffset=0¦Orientation=2¦PaperLength=1000¦PaperWidth=1000¦Scale=100¦PaperSource=15¦PrintQuality=600¦MediaType=1¦DitherType=10¦PaperKind=Letter¦PrintScaleMode=1
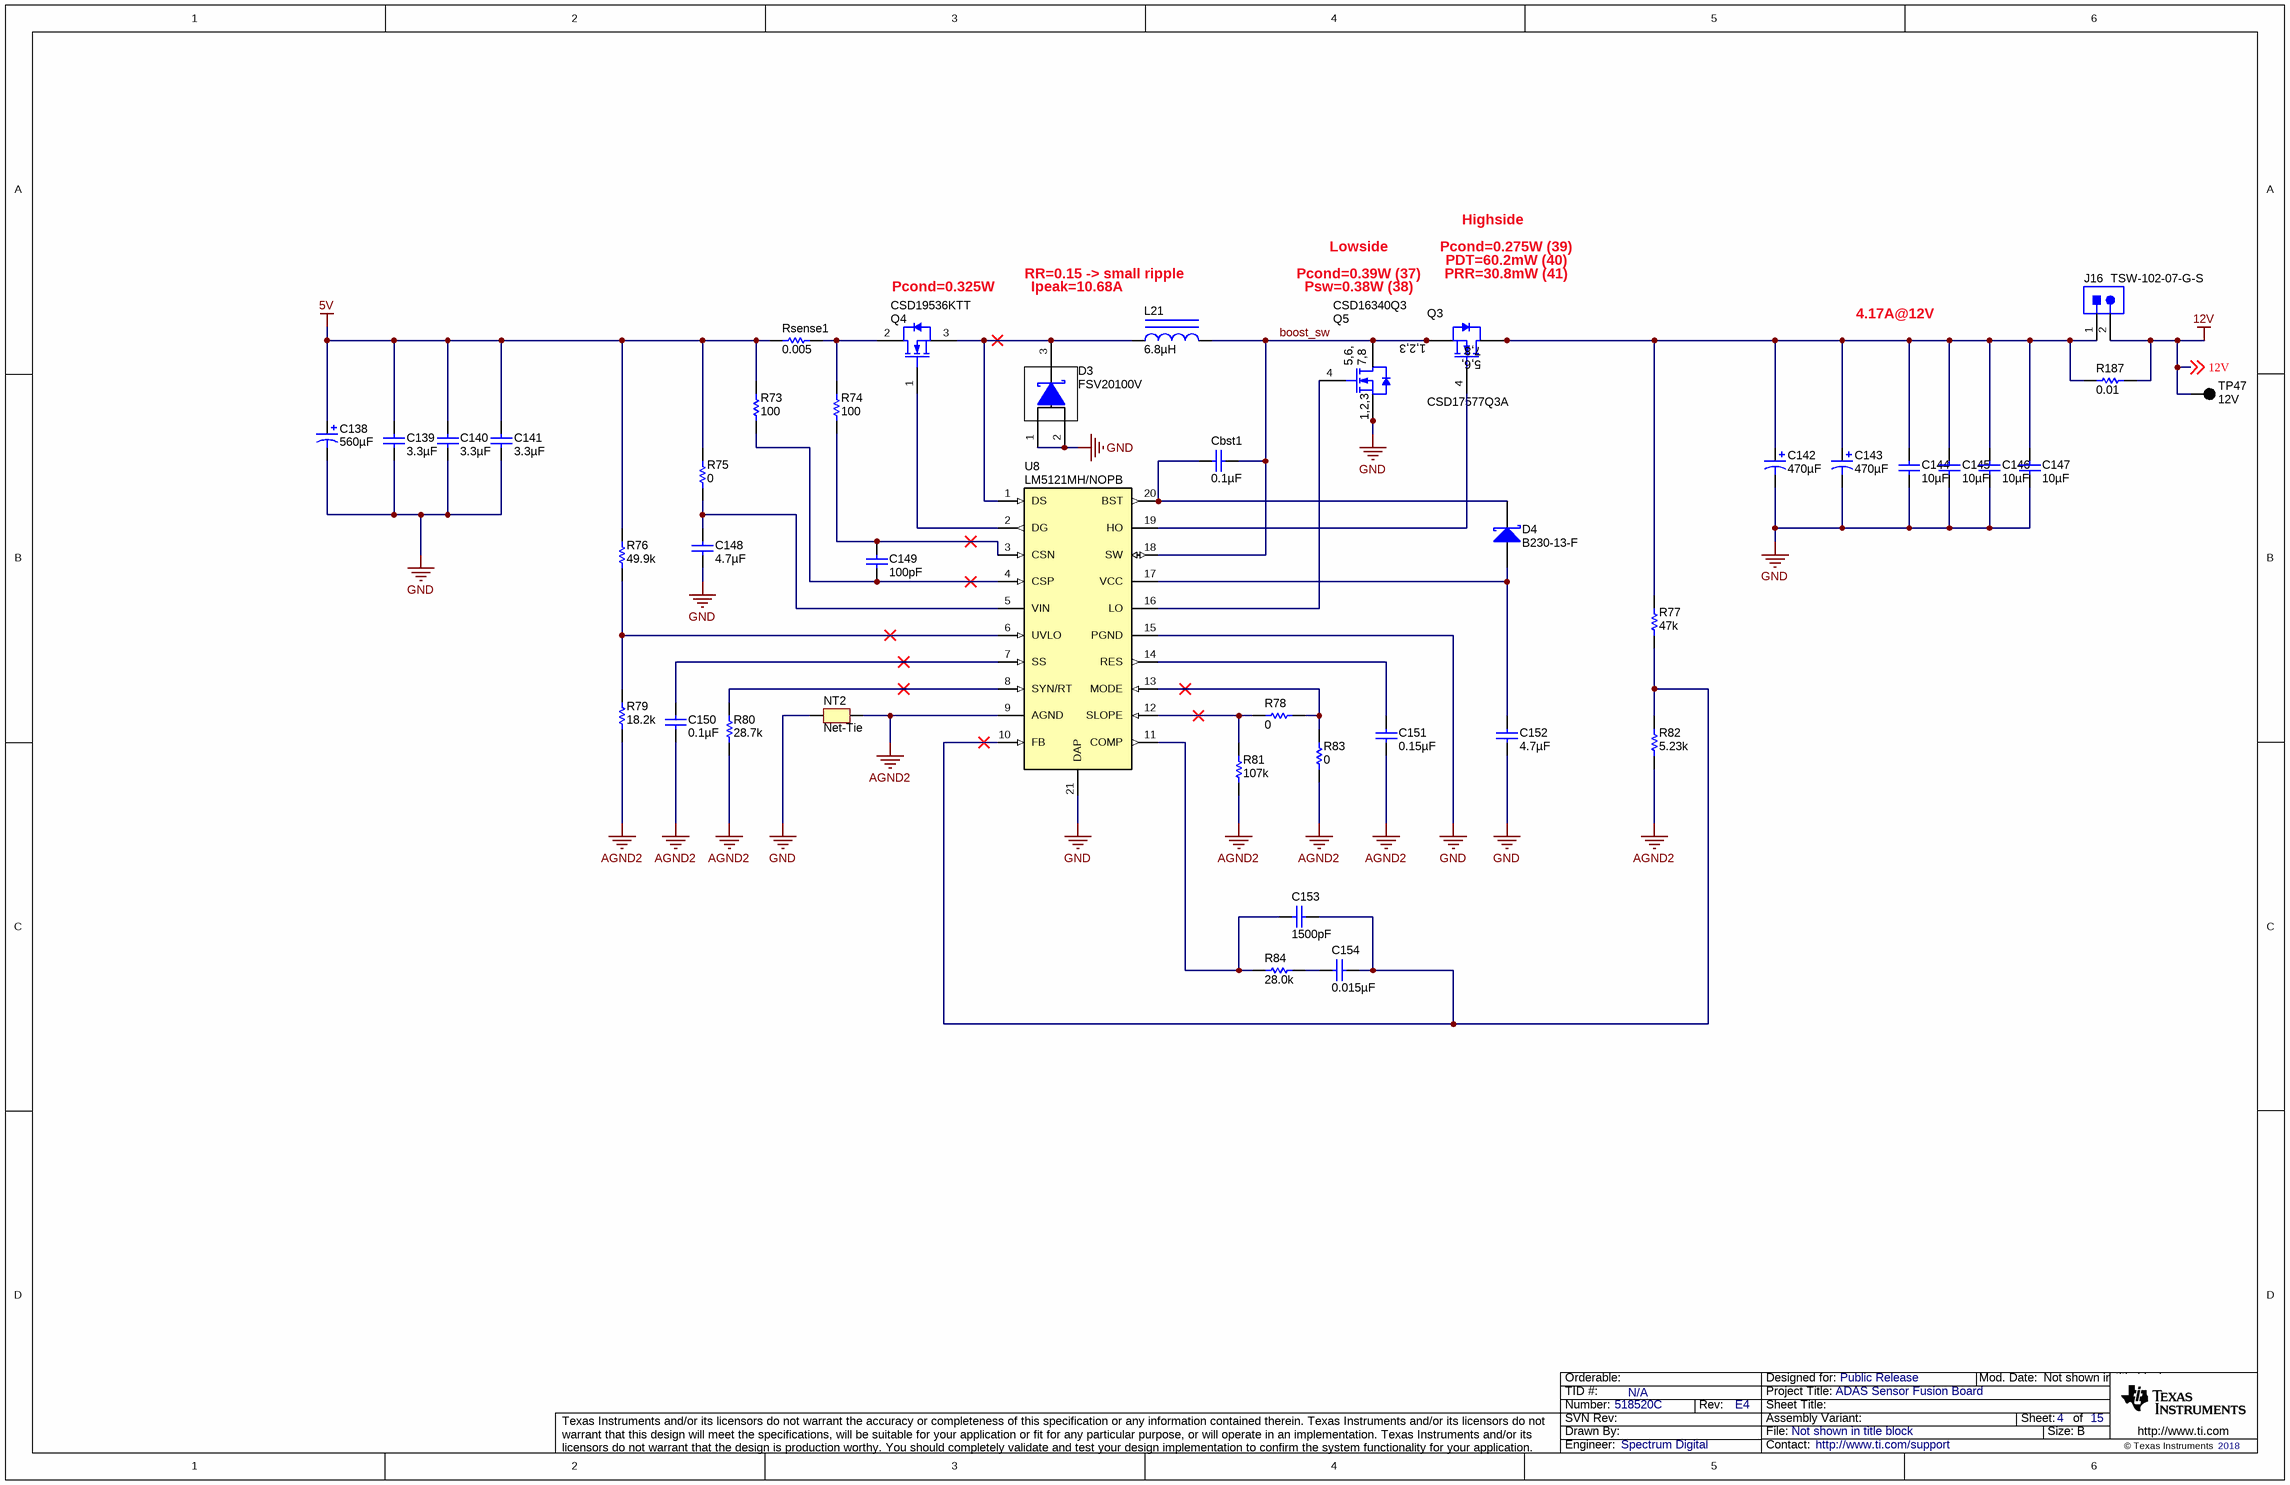
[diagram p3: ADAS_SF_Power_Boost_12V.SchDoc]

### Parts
C138  ValueDisplayed: 560µF  [Panasonic_G]  (hidden comment: EEEFPE561UAP)
C139  ValueDisplayed: 3.3µF  [0805_HV]  (hidden comment: GRM21BC81E335KA73L)
C140  ValueDisplayed: 3.3µF  [0805_HV]  (hidden comment: GRM21BC81E335KA73L)
C141  ValueDisplayed: 3.3µF  [0805_HV]  (hidden comment: GRM21BC81E335KA73L)
C142  ValueDisplayed: 470µF  [CAPSMT_62_JC0]  (hidden comment: 16SVPE470M)
C143  ValueDisplayed: 470µF  [CAPSMT_62_JC0]  (hidden comment: 16SVPE470M)
C144  ValueDisplayed: 10µF  [0805_HV]  (hidden comment: CL21A106KAFN3NE)
C145  ValueDisplayed: 10µF  [0805_HV]  (hidden comment: CL21A106KAFN3NE)
C146  ValueDisplayed: 10µF  [0805_HV]  (hidden comment: CL21A106KAFN3NE)
C147  ValueDisplayed: 10µF  [0805_HV]  (hidden comment: CL21A106KAFN3NE)
C148  ValueDisplayed: 4.7µF  [0603]  (hidden comment: GRM188R61E475KE11D)
C149  ValueDisplayed: 100pF  [0402]  (hidden comment: GRM1555C1H101JA01D)
C150  ValueDisplayed: 0.1µF  [0402]  (hidden comment: GCM155R71H104KE02D)
C151  ValueDisplayed: 0.15µF  [0402]  (hidden comment: GRM155R61A154KE19D)
C152  ValueDisplayed: 4.7µF  [0805_HV]  (hidden comment: GRM21BC71H475KE11K)
C153  ValueDisplayed: 1500pF  [0402]  (hidden comment: GRM155R71H152KA01D)
C154  ValueDisplayed: 0.015µF  [0402]  (hidden comment: CGA2B3X7R1H153K050BB)
Cbst1  ValueDisplayed: 0.1µF  [0603]  (hidden comment: GRM188R72A104KA35D)
D3  FSV20100V  [TO-277A]
D4  B230-13-F  [SMB]
J16  TSW-102-07-G-S  [TSW-102-07-G-S]
L21  ValueDisplayed: 6.8µH  [XAL1010]  (hidden comment: XAL1010-682MEB)
NT2  Net-Tie  [Net-Tie_10mil]  (net tie, no BOM)
Q3  CSD17577Q3A  [TRANS_NexFET_Q3A]
Q4  CSD19536KTT  [KTT0002A_N]
Q5  CSD16340Q3  [DQG0008A]
R73  ValueDisplayed: 100  [0402]  (hidden comment: CRCW0402100RFKED)
R74  ValueDisplayed: 100  [0402]  (hidden comment: CRCW0402100RFKED)
R75  ValueDisplayed: 0  [0603]  (hidden comment: CRCW06030000Z0EA)
R76  ValueDisplayed: 49.9k  [0402]  (hidden comment: CRCW040249K9FKED)
R77  ValueDisplayed: 47k  [0402]  (hidden comment: CRCW040247K0JNED)
R78  ValueDisplayed: 0  [0402]  (hidden comment: CRCW04020000Z0ED)
R79  ValueDisplayed: 18.2k  [0402]  (hidden comment: CRCW040218K2FKED)
R80  ValueDisplayed: 28.7k  [0402]  (hidden comment: CRCW040228K7FKED)
R81  ValueDisplayed: 107k  [0402]  (hidden comment: CRCW0402107KFKED)
R82  ValueDisplayed: 5.23k  [0402]  (hidden comment: CRCW04025K23FKED)
R83  ValueDisplayed: 0  [0402]  (hidden comment: CRCW04020000Z0ED)
R84  ValueDisplayed: 28.0k  [0402]  (hidden comment: CRCW040228K0FKED)
R187  ValueDisplayed: 0.01  [KRL2012]  (hidden comment: KRL2012E-M-R010-F-T5)
Rsense1  ValueDisplayed: 0.005  [0612]  (hidden comment: PRL1632-R005-F-T1)
TP47  12V  [Keystone5011]
U8  LM5121MH/NOPB  [PWP0020A_N]

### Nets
5V: C138.1(+) C139.1 C140.1 C141.1 R73.2 R75.2 R76.2 Rsense1.1
12V: J16.2 R187.2 TP47.1 ; off-sheet 12V
AGND2: C150.2 C151.2 NT2.1 R79.1 R80.1 R81.1 R82.1 R83.1 U8.9(AGND)
GND: C138.2(-) C139.2 C140.2 C141.2 C142.2(-) C143.2(-) C144.2 C145.2 C146.2 C147.2 C148.2 C152.2 D3.1(A) D3.2(A) NT2.2 Q5.1(S) Q5.2(S) Q5.3(S) U8.15(PGND) U8.21(DAP)
boost_sw: Cbst1.1 L21.2 Q3.1(S) Q3.2(S) Q3.3(S) Q5.5(D) Q5.6(D) Q5.7(D) Q5.8(D) Q5.9(D) U8.18(SW)
NetC142_1: C142.1(+) C143.1(+) C144.1 C145.1 C146.1 C147.1 J16.1 Q3.5(D) Q3.6(D) Q3.7(D) Q3.8(D) Q3.9(D) R77.2 R187.1
NetC148_1: C148.1 R75.1 U8.5(VIN)
NetC149_1: C149.1 R74.1 U8.3(CSN)
NetC149_2: C149.2 R73.1 U8.4(CSP)
NetC150_1: C150.1 U8.7(SS)
NetC151_1: C151.1 U8.14(RES)
NetC152_1: C152.1 D4.2(A) U8.17(VCC)
NetC153_1: C153.1 C154.1 R77.1 R82.2 U8.10(FB)
NetC153_2: C153.2 R84.1 U8.11(COMP)
NetC154_2: C154.2 R84.2
NetCbst1_2: Cbst1.2 D4.1(K) U8.20(BST)
NetD3_3: D3.3(K) L21.1 Q4.3(S) U8.1(DS)
NetQ3_4: Q3.4(G) U8.19(HO)
NetQ4_1: Q4.1(G) U8.2(DG)
NetQ4_2: Q4.2(D) R74.2 Rsense1.2
NetQ5_4: Q5.4(G) U8.16(LO)
NetR76_1: R76.1 R79.2 U8.6(UVLO)
NetR78_1: R78.1 R83.2 U8.13(MODE)
NetR78_2: R78.2 R81.2 U8.12(SLOPE)
NetR80_2: R80.2 U8.8(SYN/RT)

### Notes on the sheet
- Highside
- (near Q4) Pcond=0.325W
- Ipeak=10.68A
- RR=0.15 -> small ripple
- Pcond=0.39W (37)
- Psw=0.38W (38)
- Lowside
- Pcond=0.275W (39)
- PDT=60.2mW (40)
- PRR=30.8mW (41)
- 4.17A@12V

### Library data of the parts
C138 = EEEFPE561UAP: CAP, AL, 560 µF, 25 V, +/- 20%, 0.08 ohm, AEC-Q200 Grade 2, SMD; Manufacturer: Panasonic; Polarized: Y; CompType: Capacitor; Value: 560uF; U/M: EA; Cap_F: 0.00056; Tolerance_%: 20; VDC_V: 25; Value2: 25V; ESR_ohm: 0.08; IRMS_A: 0.85; TaMin_C: -55; TaMax_C: 105; Cap_Case: 10x10.2mm; AEC Category: Q200; AEC Grade: 2
C139-C141 = GRM21BC81E335KA73L: CAP, CERM, 3.3 µF, 25 V, +/- 10%, X6S, 0805; Manufacturer: MuRata; Polarized: N; CompType: Capacitor; Value: 3.3uF; U/M: EA; Cap_F: 0.0000033; Tolerance_%: 10; Value1: Unknown; VDC_V: 25; Value2: 25V; TaMin_C: -55; TaMax_C: 105; Cap_Case: 0805; SizeArea_mm2: 2.5; SizeAreaWB_mm2: 6.75; SizeX_mm: 2; SizeY_mm: 1.25; SizeZ_mm: 1.45; AEC Category: Q200
C142 C143 = 16SVPE470M: CAP, Aluminum Polymer, 470 µF, 16 V, +/- 20%, 0.01 ohm, JC0 SMD; Manufacturer: Panasonic; Polarized: Y; CompType: Capacitor; Value: 470uF; U/M: EA; Cap_F: 0.00047; Tolerance_%: 20; VDC_V: 16; Value2: 16V; ESR_ohm: 0.01; IRMS_A: 6.1; TaMin_C: -55; TaMax_C: 105; AEC Category: Q200
C144-C147 = CL21A106KAFN3NE: CAP, CERM, 10 µF, 25 V, +/- 10%, X5R, 0805; Manufacturer: Samsung Electro-Mechanics; Polarized: N; CompType: Capacitor; Value: 10uF; U/M: EA; Cap_F: 0.00001; Tolerance_%: 10; Value1: Unknown; VDC_V: 25; Value2: 25V; TaMin_C: -55; TaMax_C: 85; Cap_Case: 0805; SizeArea_mm2: 2.5; SizeAreaWB_mm2: 6.75; SizeX_mm: 2; SizeY_mm: 1.25; SizeZ_mm: 1.45; AEC Category: Q200
C148 = GRM188R61E475KE11D: CAP, CERM, 4.7 µF, 25 V, +/- 10%, X5R, 0603; Manufacturer: MuRata; Polarized: N; CompType: Capacitor; Value: 4.7uF; U/M: EA; Cap_F: 0.0000047; Tolerance_%: 10; Value1: Unknown; VDC_V: 25; Value2: 25V; TaMin_C: -55; TaMax_C: 85; SizeArea_mm2: 1.28; SizeAreaWB_mm2: 4.68; SizeX_mm: 1.6; SizeY_mm: 0.8; SizeZ_mm: 1; AEC Category: Q200
C149 = GRM1555C1H101JA01D: CAP, CERM, 100 pF, 50 V, +/- 5%, C0G/NP0, 0402; Manufacturer: MuRata; Polarized: N; CompType: Capacitor; Value: 100pF; U/M: EA; Cap_F: 0.0000000001; Tolerance_%: 5; Value1: Unknown; VDC_V: 50; Value2: 50V; TaMin_C: -55; TaMax_C: 125; SizeArea_mm2: 0.5; SizeAreaWB_mm2: 3; SizeX_mm: 1; SizeZ_mm: 0.6; AEC Category: Q200
C150 = GCM155R71H104KE02D: as C176 on sheet ADAS_SF_Power_Buck_5V
C151 = GRM155R61A154KE19D: CAP, CERM, 0.15 µF, 10 V, +/- 10%, X5R, 0402; Manufacturer: MuRata; Polarized: N; CompType: Capacitor; Value: 0.15uF; U/M: EA; Cap_F: 0.00000015; Tolerance_%: 10; Value1: Unknown; Value2: 10V; TaMin_C: -55; TaMax_C: 85; SizeArea_mm2: 0.5; SizeAreaWB_mm2: 3; SizeX_mm: 1; SizeZ_mm: 0.6; AEC Category: Q200
C152 = GRM21BC71H475KE11K: CAP, CERM, 4.7 µF, 50 V, +/- 10%, X7S, 0805; Manufacturer: MuRata; Polarized: N; CompType: Capacitor; Value: 4.7uF; U/M: EA; Cap_F: 0.0000047; Tolerance_%: 10; Value1: Unknown; VDC_V: 50; Value2: 50V; TaMin_C: -55; TaMax_C: 125; Cap_Case: 0805; AEC Category: Q200; SizeArea_mm2: 2.5; SizeAreaWB_mm2: 6.75; SizeX_mm: 2; SizeY_mm: 1.25; SizeZ_mm: 1.45
C153 = GRM155R71H152KA01D: CAP, CERM, 1500 pF, 50 V, +/- 10%, X7R, 0402; Manufacturer: MuRata; Polarized: N; CompType: Capacitor; Value: 1500pF; U/M: EA; Cap_F: 0.0000000015; Tolerance_%: 10; Value1: Unknown; VDC_V: 50; Value2: 50V; TaMin_C: -55; TaMax_C: 125; SizeArea_mm2: 0.5; SizeAreaWB_mm2: 3; SizeX_mm: 1; SizeZ_mm: 0.6; AEC Category: Q200
C154 = CGA2B3X7R1H153K050BB: CAP, CERM, 0.015 µF, 50 V, +/- 10%, X7R, AEC-Q200 Grade 1, 0402; Manufacturer: TDK; Polarized: N; CompType: Capacitor; Value: 0.015uF; U/M: EA; Cap_F: 0.000000015; Tolerance_%: 10; ESR_ohm: 0.2162; Value1: 0.2162 ohm; VDC_V: 50; Value2: 50V; IRMS_A: 0.379389; TaMin_C: -55; TaMax_C: 125; SizeArea_mm2: 0.5; SizeAreaWB_mm2: 3; SizeX_mm: 1; SizeZ_mm: 0.6; AEC Category: Q200; AEC Qualified: Y
Cbst1 = GRM188R72A104KA35D: CAP, CERM, 0.1 µF, 100 V, +/- 10%, X7R, 0603; Manufacturer: MuRata; Polarized: N; CompType: Capacitor; Value: 0.1uF; U/M: EA; Cap_F: 0.0000001; Tolerance_%: 10; Value1: Unknown; VDC_V: 100; Value2: 100V; TaMin_C: -55; TaMax_C: 125; AEC Category: Q200; SizeArea_mm2: 1.28; SizeAreaWB_mm2: 4.68; SizeX_mm: 1.6; SizeY_mm: 0.8; SizeZ_mm: 1
D3 = FSV20100V: Diode, Schottky, 100 V, 20 A, AEC-Q101, TO-277A; Manufacturer: Fairchild Semiconductor; U/M: EA; Vf_V: 0.66; Value: 100V; Value1: 20A; Value2: 0.66V; Io_A: 20; Vr_V: 100; TJmax_C: 150; SizeAreaWB_mm2: 56.1; SizeArea_mm2: 29.9; SizeX_mm: 4.6; SizeY_mm: 6.5; SizeZ_mm: 1.2; AEC Category: Q101; AEC Qualified: Y
D4 = B230-13-F: Diode, Schottky, 30 V, 2 A, SMB; Manufacturer: Diodes Inc.; U/M: EA; Vf_V: 0.5; Value: 30V; Value1: 2A; Value2: 0.5V; Io_A: 2; Vr_V: 30; TJmax_C: 150; RJC_CperW: 20; SizeAreaWB_mm2: 44.156; SizeArea_mm2: 21.336; SizeX_mm: 5.6; SizeY_mm: 3.81; SizeZ_mm: 2.6; AEC Category: Q101
J16 = TSW-102-07-G-S: as J12 on sheet ADAS_SF_Power_Battery_Input
L21 = XAL1010-682MEB: Inductor, Shielded, Composite, 6.8 µH, 18.5 A, 0.01 ohm, SMD; Manufacturer: Coilcraft; Value: 6.8uH; Ind_H: 6.8E-6; Imax_A: 18.5; Irms: 18.5A @ 40C rise; Isat: 21.8A @ 30% inductance drop; DCR_ohm: 0.01; Value2: 18.5A; AEC Category: Q200
NT2 = Net-Tie: as NT1 on sheet ADAS_SF_Power_Buck_5V
Q3 = CSD17577Q3A: MOSFET, N-CH, 30 V, 19 A, SON 3.3x3.3mm; Manufacturer: Texas Instruments; Alternate Manufacturer: None; U/M: EA; ChType: N; Value: 30V; VdsMax_V: 30; Value1: 0.0064 ohm; Rdson45_ohm: 0.0064; Value2: 13 nC; QgTyp_nC: 13; Vgs_V: 20; IdsMax_A: 19; AEC Category: Q101
Q4 = CSD19536KTT: MOSFET, N-CH, 100 V, 200 A, TO-263-2; Manufacturer: Texas Instruments; Alternate Manufacturer: None; U/M: EA; ChType: N; Value: 100V; VdsMax_V: 100; Value1: ? ohm; Value2: 118 nC; QgTyp_nC: 118; Vgs_V: 20; IdsMax_A: 200; SizeAreaWB_mm2: 198.208; SizeArea_mm2: 145.288; SizeX_mm: 14.3; SizeY_mm: 10.16; SizeZ_mm: 4.7; AEC Category: Q101
Q5 = CSD16340Q3: MOSFET, N-CH, 25 V, 60 A, DQG0008A; Manufacturer: Texas Instruments; Alternate Manufacturer: None; U/M: EA; ChType: N; Value: 25V; VdsMax_V: 25; Value1: 0.0043 ohm; Rdson45_ohm: 0.0043; Value2: 6.5 nC; QgTyp_nC: 6.5; Vgs_V: 10; IdsMax_A: 60; AEC Category: Q101
R73 R74 = CRCW0402100RFKED: RES, 100, 1%, 0.063 W, 0402; Manufacturer: Vishay-Dale; CompType: Resistor; Value: 100; Value_Code: 100R; Tolerance_%: 1; Power_W: 0.063; Value2: 0.063W; VDC_V: 50; TempCo: 100 ppm/C; SizeArea_mm2: 0.5; SizeZ_mm: 0.6; EIA_Code: E96; U/M: EA; AEC Category: Q200
R75 = CRCW06030000Z0EA: RES, 0, 5%, 0.1 W, 0603; Manufacturer: Vishay-Dale; CompType: Resistor; Value: 0; Value_Code: 0000; Tolerance_%: 5; Power_W: 0.1; Value2: 0.1W; VDC_V: 75; TempCo: 200 ppm/C; SizeArea_mm2: 1.28; SizeX_mm: 1.6; SizeY_mm: 0.8; SizeZ_mm: 1; EIA_Code: E24; U/M: EA; AEC Category: Q200
R76 = CRCW040249K9FKED: RES, 49.9 k, 1%, 0.063 W, 0402; Manufacturer: Vishay-Dale; CompType: Resistor; Value: 49.9k; Res_ohm: 49900; Value_Code: 49k9; Tolerance_%: 1; Power_W: 0.063; Value2: 0.063W; VDC_V: 50; TempCo: 100 ppm/C; EIA_Code: E96; U/M: EA; AEC Category: Q200
R77 = CRCW040247K0JNED: RES, 47 k, 5%, 0.063 W, 0402; Manufacturer: Vishay-Dale; CompType: Resistor; Value: 47k; Res_ohm: 47000; Value_Code: 47k0; Tolerance_%: 5; Power_W: 0.063; Value2: 0.063W; VDC_V: 50; TempCo: 200 ppm/C; SizeArea_mm2: 0.5; SizeX_mm: 1; SizeZ_mm: 0.6; EIA_Code: E24; U/M: EA; AEC Category: Q200
R78 R83 = CRCW04020000Z0ED: RES, 0, 5%, 0.063 W, 0402; Manufacturer: Vishay-Dale; CompType: Resistor; Value: 0; Value_Code: 0000; Tolerance_%: 5; Power_W: 0.063; Value2: 0.063W; VDC_V: 50; TempCo: 200 ppm/C; SizeArea_mm2: 0.5; SizeX_mm: 1; SizeZ_mm: 0.6; EIA_Code: E24; U/M: EA; AEC Category: Q200
R79 = CRCW040218K2FKED: RES, 18.2 k, 1%, 0.063 W, 0402; Manufacturer: Vishay-Dale; CompType: Resistor; Value: 18.2k; Res_ohm: 18200; Value_Code: 18k2; Tolerance_%: 1; Power_W: 0.063; Value2: 0.063W; VDC_V: 50; TempCo: 100 ppm/C; SizeArea_mm2: 0.5; SizeZ_mm: 0.6; EIA_Code: E96; U/M: EA; AEC Category: Q200
R80 = CRCW040228K7FKED: RES, 28.7 k, 1%, 0.063 W, 0402; Manufacturer: Vishay-Dale; CompType: Resistor; Value: 28.7k; Res_ohm: 28700; Value_Code: 28k7; Tolerance_%: 1; Power_W: 0.063; Value2: 0.063W; VDC_V: 50; TempCo: 100 ppm/C; EIA_Code: E96; U/M: EA; AEC Category: Q200
R81 = CRCW0402107KFKED: RES, 107 k, 1%, 0.063 W, 0402; Manufacturer: Vishay-Dale; CompType: Resistor; Value: 107k; Res_ohm: 107000; Tolerance_%: 1; Power_W: 0.063; Value2: 0.063W; VDC_V: 50; TempCo: 100 ppm/C; SizeArea_mm2: 0.5; SizeZ_mm: 0.6; EIA_Code: E96; U/M: EA; AEC Category: Q200
R82 = CRCW04025K23FKED: RES, 5.23 k, 1%, 0.063 W, 0402; Manufacturer: Vishay-Dale; CompType: Resistor; Value: 5.23k; Res_ohm: 5230; Value_Code: 5k23; Tolerance_%: 1; Power_W: 0.063; Value2: 0.063W; VDC_V: 50; TempCo: 100 ppm/C; EIA_Code: E96; U/M: EA; AEC Category: Q200
R84 = CRCW040228K0FKED: RES, 28.0 k, 1%, 0.063 W, 0402; Manufacturer: Vishay-Dale; CompType: Resistor; Value: 28.0k; Res_ohm: 28000; Value_Code: 28k0; Tolerance_%: 1; Power_W: 0.063; Value2: 0.063W; VDC_V: 50; TempCo: 100 ppm/C; EIA_Code: E96; U/M: EA; AEC Category: Q200
R187 = KRL2012E-M-R010-F-T5: as R172 on sheet ADAS_SF_Power_Battery_Input
Rsense1 = PRL1632-R005-F-T1: RES, 0.005, 1%, 1 W, 0612; Manufacturer: Susumu Co Ltd; CompType: Resistor; Value: 0.005; Value_Code: 5L000; Tolerance_%: 1; Value2: 1W; TempCo: 350 ppm/C; EIA_Code: E96; U/M: EA; AEC Category: Q200
TP47 = 5011: as TP40 on sheet ADAS_SF_Power_Battery_Input
U8 = LM5121MH/NOPB: Wide Input Synchronous Boost Controller with Disconnection Switch Control, PWP0020A; Manufacturer: Texas Instruments; SymbolCreator: a0411947; CompType: IC; U/M: EA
